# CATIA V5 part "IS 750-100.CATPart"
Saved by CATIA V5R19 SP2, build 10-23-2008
Part number: IS 750-100
Bounding box of the stored display mesh (mm): x -24.865 to 24.865, y -24.997 to 24.997, z 0 to 295
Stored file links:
  C:\Users\Bora\Desktop\3D Katı model\IS serisi\IS 750\IS 750-100.CATPart
  C:\Program Files\Dassault Systemes\B19\intel_a\reffiles\standard\MetricThickPitch.txt
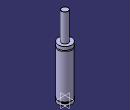
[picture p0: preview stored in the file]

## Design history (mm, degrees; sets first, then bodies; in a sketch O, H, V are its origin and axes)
Body1 (main body)
  Sketch1 on yz-plane, origin (0, 0, 0), H (0, 1, 0), V (0, 0, 1)
    point P1 (25, 179.5)
    point P2 (25, 175.5)
    point P5 (12.5, 294)
    point P7 (12.5, 294)
    point P12 (25, 175.5)
    point P13 (25, 179.5)
    arc A1 centre (25, 177.5) radius 2 from (25, 179.5) to (25, 175.5) ccw
    line L1 (25, 0) -> (25, 8)
    line L2 (12.5, 294) -> (12.5, 192)
    arc A2 centre (11.5, 294) radius 1 from (12.5, 294) to (11.5, 295) ccw
    line L3 (21.5, 13) -> (21.5, 8)
    line L4 (25, 13) -> (25, 175.5)
    line L5 (25, 179.5) -> (25, 192)
    line L6 (11.5, 295) -> (0, 295)
    point P15 (0, 295)
    line L7 (12.5, 192) -> (25, 192)
    line L8 (21.5, 13) -> (25, 13)
    line L9 (21.5, 8) -> (25, 8)
    line L10 (25, 0) -> (0, 0)
    coincidence: P15 V, P1 P13, P2 P12, P5 P7
    tangency: L6 A2
    horizontal: L7 H, L8 H, L9 H, L10 H
  Shaft1: profile Sketch1, axis Sketch1.V, angle 360
  Sketch2 on face of Shaft1 from Sketch1.L10, origin (0, 0, 0), H (1, 0, 0), V (0, -1, 0)
    point P1 (10, 0)
    distance V P1 = 10
  Hole1: placed by Sketch2, at (10, 0, 0) direction (0, 0, 1), diameter 6.647, depth 13, threaded "M8", thread diameter 8, thread depth 13, pitch 1.25
  Sketch3 on face of Shaft1 from Sketch1.L10, origin (0, 0, 0), H (1, 0, 0), V (0, -1, 0)
    point P1 (-10, 0)
    distance V P1 = 10
  Hole2: placed by Sketch3, at (-10, 0, 0) direction (0, 0, 1), diameter 6.647, depth 13, threaded "M8", thread diameter 8, thread depth 13, pitch 1.25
